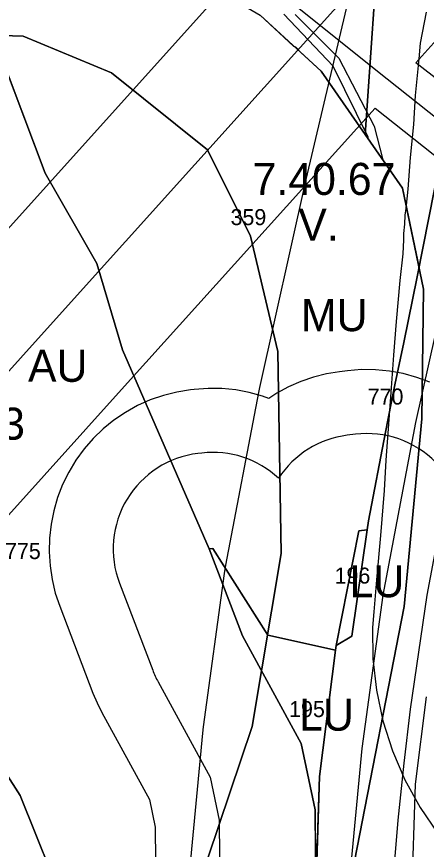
# Model space of a CAD drawing. Extents: x -690419 to -685080, y -987825 to -981190.
# Drawn here: x -687045.1 to -686917.1, y -987428.8 to -987168.9 of the extents above; entities that cross this region are included whole.
import ezdxf

# ---------------------------------------------------------------- set-up
doc = ezdxf.new("R2010")
doc.units = 0
for name, color, linetype in [('BP VTL plynovodu a RS (S)', 7, 'Continuous'), ('BPEJ (S) - hranice', 7, 'Continuous'), ('BPEJ (S) - kód', 7, 'Continuous'), ('BPEJ I-II ochrana', 7, 'Continuous'), ('Elektro VN 35 nadzemní (S)', 7, 'Continuous'), ('Elektro VVN 220 nadzemni (S)', 7, 'Continuous'), ('Elektro VVN 400 nadzemni (S)', 7, 'Continuous'), ('Lesy hospodářské', 7, 'Continuous'), ('OP elektro VN (S)', 7, 'Continuous'), ('OP lesa 30 m (S)', 7, 'Continuous'), ('OP lesa 50 m (S)', 7, 'Continuous'), ('OP silnic (S)', 7, 'Continuous'), ('Plochy dopravy silniční DS (S)', 7, 'Continuous'), ('Plochy lesní všeobecné LU (S)', 7, 'Continuous'), ('Plochy smíšené nezastavěného území všeobecné MU (S)', 7, 'Continuous'), ('Plochy zemědělské všeobecné AU (S)', 7, 'Continuous'), ('Regulacni bloky_ID', 7, 'Continuous'), ('Regulační bloky STABILIZOVANÉ (S)', 7, 'Continuous'), ('Regulační kódy STABILIZOVANÉ (S)', 7, 'Continuous'), ('Silnice I třídy (S) - osa', 7, 'Continuous')]:
    doc.layers.add(name, color=color, linetype=linetype)

msp = doc.modelspace()

# ---------------------------------------------------------------- linework, layer by layer
at = {"layer": 'BP VTL plynovodu a RS (S)'}
for points in [[(-686917.13, -987167.57), (-686919.02, -987177.21), (-686919.49, -987182.1), (-686920.58, -987193.57), (-686921.15, -987202.62), (-686922.14, -987212.88), (-686922.89, -987222.83), (-686923.48, -987228.84)], [(-686923.48, -987228.84), (-686923.79, -987230.85), (-686923.95, -987233.73)], [(-686923.95, -987233.73), (-686924.23, -987236.59), (-686924.23, -987238.62)], [(-686924.23, -987238.62), (-686924.48, -987242.94), (-686925.41, -987251.31), (-686926.52, -987264.04), (-686927.4, -987274.61), (-686928.23, -987286.29), (-686929.79, -987307.37), (-686930.28, -987316.84), (-686931.42, -987330.93), (-686932.65, -987344.69), (-686933.5, -987354.69), (-686933.92, -987359.58), (-686933.79, -987369.41), (-686932.69, -987379.17), (-686930.65, -987388.78), (-686927.67, -987398.14), (-686923.79, -987407.17), (-686919.04, -987415.77), (-686913.47, -987423.87)]]:
    msp.add_lwpolyline(points, dxfattribs=at)
at = {"layer": 'BPEJ (S) - hranice'}
for points in [[(-687013, -987513.5), (-686971.5, -987390.5), (-686962.5, -987336.5), (-686963.5, -987273.5), (-686972, -987237.5), (-686985.5, -987210.5), (-687015.5, -987186.5), (-687043, -987175), (-687056.5, -987174.58), (-687057.5, -987150)], [(-687054, -987612), (-687045.5, -987585.5), (-687041.5, -987582.5), (-687013.5, -987567.5), (-686999.5, -987565.5), (-686994.5, -987558.5), (-686979, -987528.5), (-686963, -987483.5), (-686948.5, -987456.5), (-686939.5, -987432.5), (-686924, -987353), (-686918.5, -987294.5), (-686918, -987254), (-686924.5, -987222.5), (-686936.25, -987205.68), (-686932.5, -987151.5)], [(-686932.5, -987151.5), (-686936.25, -987205.68), (-686950, -987186), (-686969, -987168.5)], [(-686969, -987168.5), (-686950, -987186), (-686936.25, -987205.68), (-686924.5, -987222.5), (-686918, -987254), (-686918.5, -987294.5), (-686924, -987353), (-686939.5, -987432.5)], [(-687057, -987470), (-687110, -987364.5), (-687137.5, -987281), (-687145.5, -987240.5), (-687146.5, -987200), (-687144, -987199.5), (-687126.44, -987251.1), (-687111.5, -987295), (-687087.5, -987344), (-687044, -987412), (-687029.5, -987448)]]:
    msp.add_lwpolyline(points, dxfattribs=at)
msp.add_lwpolyline([(-687013, -987513.5), (-687018.5, -987514), (-687024, -987497.5), (-687029.5, -987448), (-687044, -987412), (-687087.5, -987344), (-687111.5, -987295), (-687126.44, -987251.1), (-687121.5, -987219), (-687110, -987192), (-687091.5, -987176.5), (-687075.5, -987174), (-687056.5, -987174.58), (-687043, -987175), (-687015.5, -987186.5), (-686985.5, -987210.5), (-686972, -987237.5), (-686963.5, -987273.5), (-686962.5, -987336.5), (-686971.5, -987390.5)], close=True, dxfattribs=at)
at = {"layer": 'BPEJ I-II ochrana'}
for p, q in [((-686946.19, -987184.43), (-686961.61, -987168.17)), ((-686958.07, -987168.28), (-686944.47, -987181.9)), ((-686958.56, -987178.11), (-686957.97, -987178.4)), ((-686957.97, -987178.4), (-686956.56, -987179.95)), ((-686944.47, -987181.9), (-686933.41, -987203.16)), ((-686935.29, -987206.55), (-686946.19, -987184.43)), ((-686933.41, -987203.16), (-686930.69, -987213.64)), ((-686936.25, -987205.68), (-686935.12, -987207.3)), ((-686935.12, -987207.3), (-686935.29, -987206.55)), ((-686919.37, -987247.38), (-686912.76, -987213.81))]:
    msp.add_line(p, q, dxfattribs=at)
for points in [[(-687033.03, -987147.71), (-686988.5, -987157), (-686969, -987168.5), (-686958.56, -987178.11)], [(-686956.56, -987179.95), (-686950, -987186), (-686936.25, -987205.68)], [(-686930.69, -987213.64), (-686924.5, -987222.5), (-686919.37, -987247.38)]]:
    msp.add_lwpolyline(points, dxfattribs=at)
at = {"layer": 'Elektro VN 35 nadzemní (S)'}
msp.add_lwpolyline([(-686842.06, -987257.67), (-686929.31, -987188.46), (-687001.99, -987130.33), (-687044.68, -987096.41)], dxfattribs=at)
at = {"layer": 'Elektro VVN 220 nadzemni (S)'}
for points in [[(-687032.7, -987263.2), (-686751.15, -986950.62)], [(-687217.67, -987468.5), (-687032.7, -987263.2)]]:
    msp.add_lwpolyline(points, dxfattribs=at)
at = {"layer": 'Elektro VVN 400 nadzemni (S)'}
for points in [[(-687032.7, -987263.2), (-686751.15, -986950.62)], [(-687217.67, -987468.5), (-687032.7, -987263.2)]]:
    msp.add_lwpolyline(points, dxfattribs=at)
at = {"layer": 'Lesy hospodářské'}
for points in [[(-686940.39, -987362.34), (-686945.26, -987365.22), (-686938.14, -987329.38), (-686935.61, -987329.07)], [(-686950.48, -987406.07), (-686951.64, -987442.68), (-686951.83, -987416.53), (-686956.16, -987395.82), (-686974.56, -987362.18), (-686984.94, -987335.07), (-686983.75, -987334.93), (-686966.64, -987362), (-686945.45, -987366.7)]]:
    msp.add_lwpolyline(points, close=True, dxfattribs=at)
at = {"layer": 'OP elektro VN (S)'}
for points in [[(-686920.4, -987183.34), (-686799.44, -987049.06), (-686824.96, -987148.74), (-686848.21, -987239.29), (-686920.4, -987183.34)], [(-686980.45, -987160.36), (-687229.98, -987437.34)], [(-687203.89, -987498.03), (-687010.41, -987283.28), (-686933.14, -987197.49), (-686852.61, -987261.32), (-686864.18, -987494.39)]]:
    msp.add_lwpolyline(points, dxfattribs=at)
at = {"layer": 'OP lesa 30 m (S)'}
for p, q in [((-686939.26, -987299.29), (-686941.79, -987299.6)), ((-686987.26, -987305.14), (-686988.45, -987305.28)), ((-687012.96, -987345.8), (-687002.58, -987372.91))]:
    msp.add_line(p, q, dxfattribs=at)
for points in [[(-687000.88, -987376.58), (-686984.61, -987406.31), (-686981.81, -987419.74), (-686981.64, -987442.9)], [(-686921.66, -987443.63), (-686920.54, -987408.45), (-686917.06, -987381.2)]]:
    msp.add_lwpolyline(points, dxfattribs=at)
for centre, start, end in [((-686938.14, -987329.38), 96.9856, 146.9137), ((-686935.61, -987329.07), 351.8241, 96.9856), ((-686984.94, -987335.07), 96.7098, 200.9511), ((-686983.75, -987334.93), 46.962, 96.7098), ((-686974.56, -987362.18), 200.9511, 208.6772)]:
    msp.add_arc(centre, 30, start, end, dxfattribs=at)
at = {"layer": 'OP lesa 50 m (S)'}
msp.add_lwpolyline([(-686916.03, -987283.07), (-686920.11, -987281.53), (-686924.32, -987280.36), (-686928.62, -987279.56), (-686932.97, -987279.14), (-686937.34, -987279.1), (-686941.69, -987279.44), (-686944.22, -987279.75), (-686948.34, -987280.43), (-686952.39, -987281.45), (-686956.34, -987282.81), (-686960.16, -987284.49), (-686963.83, -987286.48), (-686966.32, -987288.12), (-686968.24, -987287.39), (-686972.41, -987286.23), (-686976.66, -987285.44), (-686980.96, -987285.01), (-686985.28, -987284.95), (-686989.59, -987285.27), (-686990.78, -987285.41), (-686995.06, -987286.1), (-686999.26, -987287.16), (-687003.35, -987288.58), (-687007.3, -987290.35), (-687011.09, -987292.45), (-687014.68, -987294.87), (-687018.04, -987297.6), (-687021.16, -987300.6), (-687024.01, -987303.86), (-687026.56, -987307.36), (-687028.8, -987311.07), (-687030.72, -987314.95), (-687032.28, -987318.99), (-687033.5, -987323.15), (-687034.35, -987327.39), (-687034.83, -987331.7), (-687034.93, -987336.03), (-687034.66, -987340.35), (-687034.02, -987344.63), (-687033.01, -987348.84), (-687031.64, -987352.95), (-687021.26, -987380.06), (-687019.94, -987383.16), (-687018.43, -987386.17), (-687003.59, -987413.31), (-687001.79, -987421.88), (-687001.64, -987443.04)], dxfattribs=at)
at = {"layer": 'OP silnic (S)'}
msp.add_lwpolyline([(-686918.72, -987067.01), (-686954.7, -987219.72), (-686969.25, -987284.72), (-686969.57, -987286.27), (-686979.85, -987340.1), (-686980.28, -987342.75), (-686986.78, -987390.61), (-686987.01, -987392.63), (-686990.96, -987434.34), (-686991.16, -987437.43), (-686993.35, -987504.7), (-686993.37, -987507.05), (-686992.72, -987552.35), (-686992.62, -987554.84), (-686985.65, -987663.27), (-686985.5, -987665.03), (-686982.73, -987692.8)], dxfattribs=at)
at = {"layer": 'Plochy dopravy silniční DS (S)'}
for p, q in [((-686919.92, -987250.19), (-686912.76, -987213.81)), ((-686924.17, -987270.69), (-686919.92, -987250.19)), ((-686926.91, -987283.89), (-686924.17, -987270.69)), ((-686928.09, -987289.58), (-686926.91, -987283.89)), ((-686929.85, -987298.64), (-686928.09, -987289.58)), ((-686935.21, -987326.26), (-686929.85, -987298.64)), ((-686935.61, -987329.07), (-686935.21, -987326.26)), ((-686940.39, -987362.34), (-686935.61, -987329.07)), ((-686945.26, -987365.22), (-686940.39, -987362.34)), ((-686945.45, -987366.7), (-686945.26, -987365.22)), ((-686950.48, -987406.07), (-686945.45, -987366.7)), ((-686951.64, -987442.68), (-686950.48, -987406.07))]:
    msp.add_line(p, q, dxfattribs=at)
at = {"layer": 'Plochy lesní všeobecné LU (S)'}
for points in [[(-686935.61, -987329.07), (-686940.39, -987362.34), (-686945.26, -987365.22), (-686938.14, -987329.38)], [(-686951.64, -987442.68), (-686951.83, -987416.53), (-686956.16, -987395.82), (-686974.56, -987362.18), (-686984.94, -987335.07), (-686983.75, -987334.93), (-686966.64, -987362), (-686945.45, -987366.7), (-686950.48, -987406.07)]]:
    msp.add_lwpolyline(points, close=True, dxfattribs=at)
at = {"layer": 'Plochy smíšené nezastavěného území všeobecné MU (S)'}
msp.add_lwpolyline([(-686904.51, -987166.69), (-686905.7, -987172.32), (-686907.28, -987181.6), (-686910.39, -987199.89), (-686912.76, -987213.81), (-686919.92, -987250.19), (-686924.17, -987270.69), (-686926.91, -987283.89), (-686928.09, -987289.58), (-686929.85, -987298.64), (-686935.21, -987326.26), (-686935.61, -987329.07), (-686938.14, -987329.38), (-686945.26, -987365.22), (-686945.45, -987366.7), (-686966.64, -987362), (-686983.75, -987334.93), (-686984.94, -987335.07), (-687012.07, -987272.93), (-687020.09, -987245.98), (-687036.16, -987217.77), (-687052.28, -987175.23), (-687058.33, -987146.42)], dxfattribs=at)
at = {"layer": 'Plochy zemědělské všeobecné AU (S)'}
for p, q in [((-687052.28, -987175.23), (-687036.16, -987217.77)), ((-687036.16, -987217.77), (-687020.09, -987245.98)), ((-687020.09, -987245.98), (-687012.07, -987272.93)), ((-687012.07, -987272.93), (-686984.94, -987335.07)), ((-686984.94, -987335.07), (-686974.56, -987362.18)), ((-686974.56, -987362.18), (-686956.16, -987395.82)), ((-686956.16, -987395.82), (-686951.83, -987416.53)), ((-686951.83, -987416.53), (-686951.64, -987442.68))]:
    msp.add_line(p, q, dxfattribs=at)
at = {"layer": 'Regulační bloky STABILIZOVANÉ (S)'}
for p, q in [((-687052.28, -987175.23), (-687036.16, -987217.77)), ((-686919.92, -987250.19), (-686912.76, -987213.81)), ((-687036.16, -987217.77), (-687020.09, -987245.98)), ((-687020.09, -987245.98), (-687012.07, -987272.93)), ((-686924.17, -987270.69), (-686919.92, -987250.19)), ((-686926.91, -987283.89), (-686924.17, -987270.69)), ((-687012.07, -987272.93), (-686984.94, -987335.07)), ((-686928.09, -987289.58), (-686926.91, -987283.89)), ((-686929.85, -987298.64), (-686928.09, -987289.58)), ((-686935.21, -987326.26), (-686929.85, -987298.64)), ((-686935.61, -987329.07), (-686935.21, -987326.26)), ((-686940.39, -987362.34), (-686935.61, -987329.07)), ((-686984.94, -987335.07), (-686974.56, -987362.18)), ((-686974.56, -987362.18), (-686956.16, -987395.82)), ((-686945.26, -987365.22), (-686940.39, -987362.34)), ((-686945.45, -987366.7), (-686945.26, -987365.22)), ((-686950.48, -987406.07), (-686945.45, -987366.7)), ((-686956.16, -987395.82), (-686951.83, -987416.53)), ((-686951.64, -987442.68), (-686950.48, -987406.07)), ((-686951.83, -987416.53), (-686951.64, -987442.68))]:
    msp.add_line(p, q, dxfattribs=at)
msp.add_lwpolyline([(-686904.51, -987166.69), (-686905.7, -987172.32), (-686907.28, -987181.6), (-686910.39, -987199.89), (-686912.76, -987213.81), (-686919.92, -987250.19), (-686924.17, -987270.69), (-686926.91, -987283.89), (-686928.09, -987289.58), (-686929.85, -987298.64), (-686935.21, -987326.26), (-686935.61, -987329.07), (-686938.14, -987329.38), (-686945.26, -987365.22), (-686945.45, -987366.7), (-686966.64, -987362), (-686983.75, -987334.93), (-686984.94, -987335.07), (-687012.07, -987272.93), (-687020.09, -987245.98), (-687036.16, -987217.77), (-687052.28, -987175.23), (-687058.33, -987146.42)], dxfattribs=at)
for points in [[(-686935.61, -987329.07), (-686940.39, -987362.34), (-686945.26, -987365.22), (-686938.14, -987329.38)], [(-686951.64, -987442.68), (-686951.83, -987416.53), (-686956.16, -987395.82), (-686974.56, -987362.18), (-686984.94, -987335.07), (-686983.75, -987334.93), (-686966.64, -987362), (-686945.45, -987366.7), (-686950.48, -987406.07)]]:
    msp.add_lwpolyline(points, close=True, dxfattribs=at)
at = {"layer": 'Silnice I třídy (S) - osa'}
for points in [[(-686870.04, -987078.45), (-686905.97, -987230.91), (-686920.46, -987295.64), (-686930.73, -987349.48), (-686937.23, -987397.34), (-686941.18, -987439.06), (-686943.38, -987506.33), (-686942.72, -987551.62), (-686935.75, -987660.06), (-686933.21, -987685.55)], [(-686921.2, -987672.45), (-686921.23, -987672.13), (-686924.41, -987638.32), (-686927.18, -987600.77), (-686928.25, -987588.15), (-686929.09, -987564.97), (-686929.8, -987547.03), (-686930.28, -987528.38), (-686930.28, -987495.44), (-686929.8, -987476.55), (-686928.77, -987456.94), (-686927.5, -987438.61), (-686925.91, -987419.72), (-686924.01, -987401.94), (-686922.02, -987385.11), (-686916.86, -987349.55), (-686910.28, -987314.78), (-686902.5, -987278.27), (-686894.72, -987244.61), (-686881.54, -987188.66), (-686877.81, -987172.54), (-686869.48, -987136.82)]]:
    msp.add_lwpolyline(points, dxfattribs=at)

# ---------------------------------------------------------------- texts
at = {"layer": 'BPEJ (S) - kód'}
for s, p in [('7.40.67', (-686971.38, -987224.59)), ('V.', (-686957.1, -987238.84)), ('7.22.13', (-687087.13, -987300.98))]:
    msp.add_text(s, height=10, dxfattribs=at).set_placement(p)
at = {"layer": 'Regulacni bloky_ID'}
for s, p in [('359', (-686978.26, -987234.01)), ('770', (-686935.42, -987290.02)), ('775', (-687048.71, -987338.24)), ('196', (-686945.77, -987345.9)), ('195', (-686959.97, -987387.56))]:
    msp.add_text(s, height=5, dxfattribs=at).set_placement(p)
at = {"layer": 'Regulační kódy STABILIZOVANÉ (S)'}
for s, p in [('MU', (-686956.28, -987267.11)), ('AU', (-687041.54, -987282.91)), ('LU', (-686941.11, -987350.15)), ('LU', (-686956.85, -987391.81))]:
    msp.add_text(s, height=10, dxfattribs=at).set_placement(p)

doc.saveas('drawing.dxf')
